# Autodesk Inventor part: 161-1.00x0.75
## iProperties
Created: 2007-06
Part Number: 161-1.00x0.75
Document SubType Name: Modeling
Designer: btaylor
Density: 1 g/cm^3
Author: btaylor
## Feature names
1. Extrusion1
2. Extrusion2
3. Extrusion3
4. Extrusion4
5. Extrusion5
6. Fillet1
7. Fillet2
8. Fillet3
9. Fillet4
10. Extrusion6
11. Extrusion7
12. Extrusion8
13. Extrusion9
14. Extrusion10
15. Fillet5
16. Fillet6
17. Fillet7
18. Fillet8
19. Chamfer1
20. Chamfer2
21. Chamfer3
22. Fillet9
23. Fillet10
24. Fillet11
